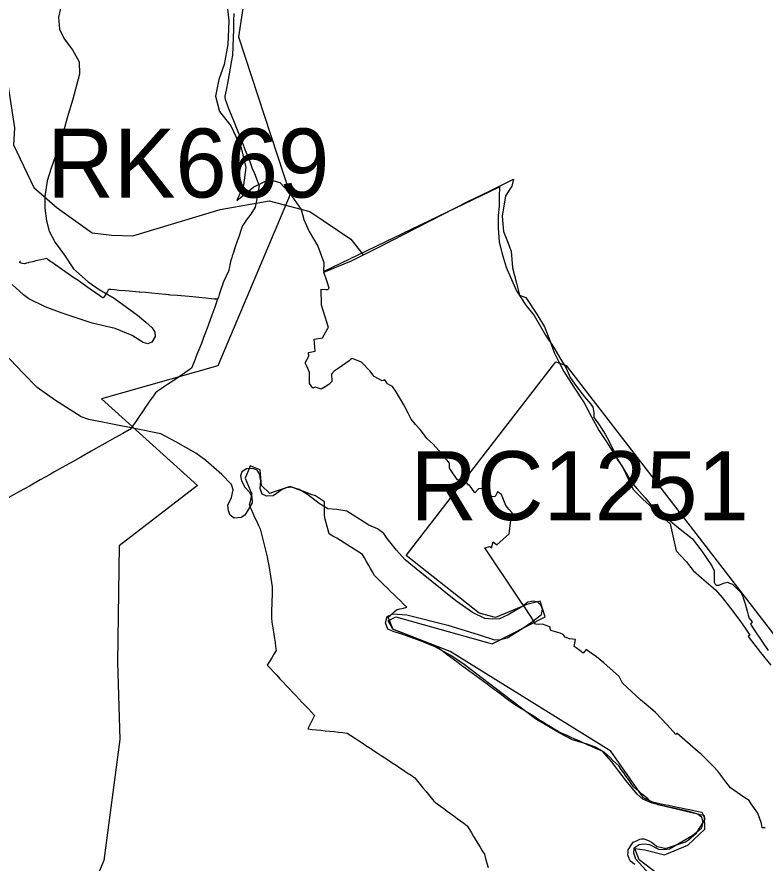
# Model space of a CAD drawing. Extents: x -789162 to -606354, y -1062736 to -945481.
# Drawn here: x -682484 to -680858, y -988999 to -987160 of the extents above; entities that cross this region are included whole.
import ezdxf

# ---------------------------------------------------------------- set-up
doc = ezdxf.new("R2010")
doc.units = 0
for name, color, linetype in [('_SIRSI VZTAHY_CYKLOTRASY MISTNI S', 7, 'Continuous'), ('_SIRSI VZTAHY_NATURA_EVL', 7, 'Continuous'), ('_SIRSI VZTAHY_OP vodnich zdroju II stupne', 7, 'Continuous'), ('_SIRSI VZTAHY_PRIRODNIHO PARKU', 7, 'Continuous'), ('_SIRSI VZTAHY_SILNICE III TRIDY_STAV', 7, 'Continuous'), ('_SIRSI VZTAHY_USES_popis S', 7, 'Continuous'), ('_SIRSI VZTAHY_USES_RBC_S', 7, 'Continuous'), ('_SIRSI VZTAHY_USES_RBK_S', 7, 'Continuous'), ('_SIRSI VZTAHY_VTL PLYNOVOD', 7, 'Continuous')]:
    doc.layers.add(name, color=color, linetype=linetype)

msp = doc.modelspace()

# ---------------------------------------------------------------- linework, layer by layer
at = {"layer": '_SIRSI VZTAHY_CYKLOTRASY MISTNI S'}
msp.add_lwpolyline([(-681958.5, -986912.3), (-682002.9, -987203.1), (-681890.1, -987545.3), (-682047.4, -987918.3), (-682300.4, -987990.2), (-682091.8, -988178.4), (-682261.9, -988309.2), (-682265.4, -988562.4), (-682260.7, -988730.8), (-682295.3, -988993.7), (-682321.8, -989054.9)], dxfattribs=at)
at = {"layer": '_SIRSI VZTAHY_NATURA_EVL'}
msp.add_lwpolyline([(-681141.3, -989002.4), (-681146.2, -988998.5), (-681151.2, -988994.6), (-681154.6, -988986), (-681156.1, -988981.6), (-681155.6, -988976.6), (-681155.6, -988970.2), (-681152.9, -988966.3), (-681148.7, -988960.1), (-681144.5, -988954), (-681142.6, -988952.8), (-681139.1, -988951.8), (-681137.1, -988951), (-681130.1, -988947.3), (-681127.2, -988946.8), (-681121, -988946.3), (-681115.7, -988948.7), (-681110.1, -988951.1), (-681104.5, -988953.6), (-681098.9, -988958.3), (-681093.2, -988963.1), (-681085, -988964.9), (-681076.8, -988966.7), (-681076.1, -988966.6), (-681075.4, -988967), (-681074.3, -988967.2), (-681065.6, -988964.5), (-681056.8, -988961.7), (-681048.1, -988958.9), (-681039.3, -988956.1), (-681030.6, -988953.4), (-681024.7, -988948.6), (-681018.8, -988943.8), (-681012.9, -988938.9), (-681007.1, -988934.1), (-681002.3, -988926.4), (-680997.5, -988918.7), (-680992.7, -988910.9), (-680987.9, -988903.2), (-680991.1, -988896.3), (-680994.3, -988889.3), (-681003.4, -988887.5), (-681012.6, -988885.7), (-681021.7, -988883.8), (-681030.9, -988882), (-681040, -988880.2), (-681049.2, -988878.3), (-681058.3, -988876.5), (-681067.7, -988874.4), (-681077.1, -988872.3), (-681086.5, -988870.1), (-681095.9, -988868), (-681105.3, -988865.8), (-681111.7, -988860.5), (-681118.1, -988855.2), (-681124.5, -988849.8), (-681130.9, -988844.5), (-681137.3, -988839.2), (-681143.7, -988833.8), (-681149, -988826.2), (-681154.3, -988818.5), (-681159.7, -988810.9), (-681165, -988803.2), (-681170.4, -988795.6), (-681175.7, -988787.9), (-681182.1, -988782), (-681188.5, -988776), (-681194.9, -988770), (-681201.3, -988764), (-681207.7, -988758.1), (-681216.8, -988754), (-681225.9, -988749.9), (-681235.1, -988745.8), (-681244.2, -988741.8), (-681253.3, -988737.7), (-681262.4, -988733.6), (-681271.5, -988729.5), (-681280.7, -988725.5), (-681289.8, -988721.4), (-681298.9, -988717.3), (-681308, -988713.2), (-681316.3, -988708.1), (-681324.6, -988702.9), (-681332.8, -988697.8), (-681341.1, -988692.6), (-681349.4, -988687.5), (-681357.6, -988682.3), (-681365.9, -988677.1), (-681374.2, -988672), (-681382.5, -988666.8), (-681390.7, -988661.7), (-681399, -988656.5), (-681407.3, -988651.3), (-681415.1, -988645.5), (-681423, -988639.7), (-681430.9, -988633.8), (-681438.8, -988628), (-681446.7, -988622.1), (-681454.5, -988616.3), (-681462.4, -988610.4), (-681470.3, -988604.6), (-681478.2, -988598.7), (-681486, -988592.9), (-681493.9, -988587.1), (-681501.8, -988581.2), (-681509.7, -988575.4), (-681517.5, -988569.5), (-681525.4, -988563.7), (-681533.3, -988557.8), (-681541.2, -988552), (-681549, -988546.2), (-681556.9, -988540.3), (-681564.8, -988534.5), (-681572.7, -988528.6), (-681581.2, -988525.1), (-681589.8, -988521.5), (-681598.3, -988517.9), (-681606.8, -988514.4), (-681615.4, -988510.8), (-681623.9, -988507.3), (-681632.4, -988504.1), (-681641, -988500.9), (-681649.5, -988497.7), (-681658.1, -988494.5), (-681666.6, -988491.3), (-681670.1, -988482.4), (-681673.7, -988473.5), (-681677.3, -988464.6), (-681671.2, -988459.3), (-681665.2, -988453.9), (-681659.1, -988448.6), (-681651.6, -988446.8), (-681644.2, -988445), (-681636.7, -988443.2), (-681643.8, -988436.3), (-681650.8, -988429.4), (-681657.8, -988422.4), (-681664.9, -988415.5), (-681671.9, -988408.6), (-681679, -988401.6), (-681686, -988394.7), (-681693.1, -988387.8), (-681700.1, -988380.8), (-681707.1, -988373.9), (-681711.4, -988366.2), (-681715.7, -988358.6), (-681719.9, -988350.9), (-681724.2, -988343.3), (-681728.5, -988335.6), (-681732.8, -988328), (-681740.8, -988323), (-681748.9, -988318), (-681756.9, -988313.1), (-681765, -988308.1), (-681773.1, -988303.1), (-681781.1, -988298.1), (-681789.2, -988293.1), (-681797.3, -988288.2), (-681805.3, -988283.2), (-681807.5, -988275.3), (-681809.6, -988267.4), (-681811.7, -988259.5), (-681813.9, -988251.6), (-681816, -988243.7), (-681816, -988233.7), (-681816, -988223.8), (-681816, -988213.8), (-681822.4, -988209.5), (-681828.8, -988205.3), (-681835.2, -988201), (-681844.3, -988197.6), (-681853.5, -988194.2), (-681862.6, -988190.8), (-681871.8, -988187.4), (-681880.9, -988184), (-681890.1, -988180.6), (-681898.9, -988183.6), (-681907.7, -988186.5), (-681916.6, -988189.5), (-681925.4, -988192.4), (-681934.2, -988195.4), (-681940.3, -988189.8), (-681946.5, -988184.2), (-681952.6, -988178.6), (-681953.4, -988170.1), (-681954.2, -988161.5), (-681955, -988153), (-681955.8, -988144.4), (-681962.9, -988141.6), (-681970, -988138.7), (-681977.1, -988135.9), (-681980.7, -988144.8), (-681984.3, -988153.7), (-681987.8, -988162.6), (-681984.3, -988171.1), (-681980.9, -988179.7), (-681977.4, -988188.2), (-681973.9, -988196.7), (-681975.7, -988204.9), (-681977.5, -988213.1), (-681979.3, -988221.3), (-681975.4, -988229.8), (-681971.4, -988238.4), (-681967.5, -988246.9), (-681963.6, -988255.4), (-681959.7, -988264), (-681955.8, -988272.5), (-681953.6, -988281.2), (-681951.3, -988290), (-681949.1, -988298.7), (-681946.8, -988307.5), (-681944.6, -988316.2), (-681942.4, -988325), (-681940.1, -988333.7), (-681938.5, -988343), (-681937, -988352.2), (-681935.4, -988361.5), (-681933.8, -988370.7), (-681932.3, -988379.9), (-681930.7, -988389.2), (-681929.1, -988398.4), (-681929.4, -988408.2), (-681929.7, -988417.9), (-681930, -988427.7), (-681930.3, -988437.5), (-681930.6, -988447.2), (-681930.9, -988457), (-681931.2, -988466.7), (-681929.9, -988475.5), (-681928.6, -988484.3), (-681927.2, -988493.1), (-681925.9, -988501.9), (-681924.6, -988510.7), (-681923.2, -988519.6), (-681921.9, -988528.4), (-681920.6, -988537.2), (-681925.5, -988545.2), (-681930.3, -988553.2), (-681935.2, -988561.2), (-681940.1, -988569.2), (-681933.2, -988576.5), (-681926.4, -988583.8), (-681919.5, -988591), (-681912.6, -988598.3), (-681905.8, -988605.6), (-681898.9, -988612.8), (-681892, -988620.1), (-681885.2, -988627.3), (-681878.3, -988634.6), (-681871.4, -988641.9), (-681864.6, -988649.1), (-681857.7, -988656.4), (-681850.8, -988663.7), (-681843.9, -988670.9), (-681837.1, -988678.2), (-681840.8, -988685.5), (-681844.4, -988692.9), (-681848.1, -988700.3), (-681851.8, -988707.6), (-681842.3, -988708.6), (-681832.8, -988709.6), (-681823.3, -988710.6), (-681813.9, -988711.5), (-681804.4, -988712.5), (-681794.9, -988713.5), (-681785.4, -988714.5), (-681775.9, -988715.5), (-681766.4, -988716.5), (-681758.2, -988721.8), (-681750.1, -988727.2), (-681741.9, -988732.6), (-681733.7, -988738), (-681725.5, -988743.4), (-681717.4, -988748.8), (-681709.2, -988754.2), (-681701, -988759.6), (-681692.8, -988765), (-681684.6, -988770.4), (-681676.5, -988775.8), (-681668.3, -988781.2), (-681660.1, -988786.6), (-681651.9, -988792), (-681643.8, -988797.4), (-681635.6, -988802.8), (-681627.4, -988808.2), (-681619.2, -988813.6), (-681613.3, -988820.9), (-681607.4, -988828.2), (-681601.6, -988835.5), (-681595.7, -988842.8), (-681589.8, -988850.2), (-681583.9, -988857.5), (-681578, -988864.8), (-681570.8, -988870.1), (-681563.5, -988875.5), (-681556.2, -988880.8), (-681549, -988886.1), (-681541.7, -988891.5), (-681534.5, -988896.8), (-681527.2, -988902.1), (-681520, -988907.5), (-681512.7, -988912.8), (-681505.4, -988918.1), (-681500.8, -988925.9), (-681496.1, -988933.6), (-681491.4, -988941.3), (-681486.8, -988949.1), (-681482.1, -988956.8), (-681477.4, -988964.6), (-681472.8, -988972.3), (-681468.1, -988980), (-681465.4, -988989.6), (-681462.8, -988999.2), (-681460.1, -989008.8)], dxfattribs=at)
at = {"layer": '_SIRSI VZTAHY_OP vodnich zdroju II stupne'}
msp.add_lwpolyline([(-680666.4, -989347.1), (-681131.4, -988992.2), (-681140.7, -988967.6), (-681119.3, -988970.2), (-681076.6, -988981.2), (-681025.7, -988960.4), (-680989, -988925.6), (-680989.5, -988896.8), (-681090.2, -988872.9), (-681121.9, -988857.5), (-681193.5, -988755.8), (-681542.5, -988539.2), (-681667.4, -988490.8), (-681676.9, -988472.2), (-681660.4, -988464.2), (-681451, -988522.3), (-681336.1, -988464), (-681347, -988429.5), (-681376.1, -988437.1), (-681443.6, -988465.3), (-681479.5, -988456.2), (-681638.4, -988330.2), (-681313.1, -987909.4), (-681290.2, -987917.1), (-680724.2, -988650.9)], dxfattribs=at)
at = {"layer": '_SIRSI VZTAHY_PRIRODNIHO PARKU'}
msp.add_lwpolyline([(-682029.7, -987115.8), (-682023.6, -987168.2), (-682025.6, -987219.6), (-682033.9, -987262.7), (-682045.2, -987295.6), (-682052.3, -987331.5), (-682044.1, -987365.4), (-682019.5, -987396.2), (-681996.9, -987444.5), (-681986.6, -987486.6), (-681991.7, -987525.6), (-682006.1, -987558.5), (-681969.1, -987528.7), (-681936.3, -987513.3), (-681912.7, -987519.5), (-681892.1, -987542.1), (-681866.4, -987578), (-681860.3, -987599.6), (-681849, -987626.3), (-681830.5, -987658.1), (-681817.1, -987693.1), (-681818.1, -987713.2), (-681435.1, -987529.2), (-681436.1, -987551), (-681436.1, -987571.2), (-681438.4, -987591.3), (-681438.4, -987618.2), (-681436.1, -987649.6), (-681429.4, -987674.3), (-681420.4, -987703.4), (-681409.2, -987730.3), (-681398, -987754.9), (-681377.8, -987786.3), (-681359.9, -987808.7), (-681335.3, -987851.3), (-681317.3, -987878.2), (-681303.9, -987900.6), (-681290.4, -987923), (-681281.5, -987943.2), (-681268, -987963.4), (-681250.1, -987985.8), (-681236.7, -988001.5), (-681232.2, -988008.2), (-681229.9, -988019.4), (-681229.9, -988030.6), (-681223.2, -988039.6), (-681214.2, -988053), (-681205.3, -988066.5), (-681198.6, -988079.9), (-681187.4, -988102.3), (-681178.4, -988122.5), (-681169.4, -988135.9), (-681159.3, -988153.2), (-681148.1, -988171.2), (-681136.9, -988184.6), (-681118.9, -988204.8), (-681107.7, -988218.2), (-681094.3, -988229.4), (-681080.8, -988240.6), (-681065.1, -988254.1), (-681049.4, -988267.5), (-681029.3, -988283.2), (-681015.8, -988294.4), (-681006.9, -988305.6), (-680995.7, -988321.3), (-680984.5, -988337), (-680973.3, -988352.7), (-680968.8, -988363.9), (-680968.8, -988379.6), (-680968.8, -988388.5), (-680966.5, -988393), (-680964.3, -988395.3), (-680957.6, -988395.3), (-680948.6, -988390.8), (-680939.6, -988388.5), (-680935.2, -988390.8), (-680928.4, -988393), (-680921.7, -988399.8), (-680915, -988406.5), (-680910.5, -988411), (-680906, -988419.9), (-680905.3, -988422.6), (-680901.5, -988435.6), (-680897.1, -988451.3), (-680894.8, -988460.3), (-680892.6, -988467), (-680886.3, -988474.9), (-680889.3, -988479.6), (-680877.4, -988498.7), (-680851.1, -988536.9)], dxfattribs=at)
at = {"layer": '_SIRSI VZTAHY_SILNICE III TRIDY_STAV'}
for points in [[(-682388.3, -987134.8), (-682393.9, -987159.7), (-682391.5, -987185.9), (-682381.6, -987207), (-682363.7, -987231.4), (-682348.8, -987256.8), (-682348.1, -987284.2), (-682362.9, -987338.2), (-682374.9, -987378.7), (-682387.6, -987424.7), (-682409.6, -987488), (-682418.3, -987515.6), (-682423.4, -987550), (-682423.8, -987575.3), (-682420.2, -987602.5), (-682413.9, -987625.4), (-682401.4, -987650.2), (-682381.1, -987677.3), (-682361.4, -987707.2), (-682329.3, -987735.2), (-682305.7, -987752.3), (-682272.9, -987771), (-682222.5, -987807.8), (-682204.2, -987823.5), (-682190.1, -987835.8), (-682184.6, -987844.7), (-682184.1, -987854.6), (-682190.9, -987866.5), (-682199.5, -987870), (-682210.2, -987867.4), (-682234.1, -987851.9), (-682270.7, -987836.6), (-682320.6, -987825.2), (-682385.8, -987803.4), (-682423.1, -987789.8), (-682458.4, -987772.8), (-682469.9, -987763.5), (-682494.9, -987741.1)], [(-681095.8, -989037.8), (-681138.7, -988990.5), (-681143, -988977.4), (-681142.4, -988966.3), (-681131.7, -988958.8), (-681120.4, -988957.3), (-681108.8, -988959), (-681089.8, -988969.2), (-681075.7, -988969.7), (-681065.7, -988968.2), (-681014.7, -988938.7), (-680995.6, -988922.5), (-680992.7, -988910.7), (-680995.5, -988900.3), (-681004.2, -988893), (-681022.8, -988887.3), (-681079.3, -988874.6), (-681103.7, -988869.2), (-681123.4, -988860), (-681135.7, -988849.1), (-681160.2, -988820.6), (-681191.7, -988778.1), (-681211, -988755.8), (-681226.2, -988747.1), (-681244.6, -988741), (-681276.5, -988731.4), (-681305.7, -988715.8), (-681357.1, -988685.4), (-681444.3, -988618.9), (-681512, -988567.8), (-681540.9, -988547.9), (-681576.6, -988528.1), (-681611.1, -988514.5), (-681645.5, -988502.2), (-681663.9, -988496.4), (-681678.1, -988490.4), (-681682.8, -988476.9), (-681679.7, -988463.4), (-681667, -988457.1), (-681636.5, -988459.8), (-681547.2, -988481.8), (-681479.3, -988503.1), (-681446.3, -988513.9), (-681433.3, -988513), (-681418.4, -988509.5), (-681386.9, -988490.1), (-681365.6, -988475.6), (-681344.1, -988459.1), (-681341.5, -988447.2), (-681345.3, -988438.6), (-681352.2, -988431.7), (-681361.1, -988429.8), (-681373.8, -988432), (-681384.6, -988440.7), (-681416.6, -988459.8), (-681435.2, -988468.1), (-681451.4, -988469.1), (-681467, -988467.2), (-681493.9, -988454.5), (-681529.8, -988428.8), (-681608.6, -988365.9), (-681640.6, -988340.2), (-681659, -988318.7), (-681679.3, -988293.8), (-681686.7, -988282.9), (-681700.1, -988272.2), (-681719.6, -988264.7), (-681739.8, -988251.2), (-681767.2, -988233.8), (-681788.9, -988230.3), (-681808.1, -988229.4), (-681827.2, -988217.1), (-681852.3, -988197.9), (-681870.4, -988187.1), (-681887.1, -988182.2), (-681899.2, -988183.2), (-681907.8, -988187.1), (-681927.4, -988201.1), (-681941.7, -988201.4), (-681951, -988197.4), (-681955.4, -988185.1), (-681954.4, -988168), (-681956.9, -988152.6), (-681962.3, -988145.3), (-681971.5, -988141.5), (-681985.3, -988141.9), (-681995.6, -988148.7), (-681998.5, -988157.6), (-681996.2, -988168), (-681988.6, -988182.2), (-681979.4, -988191.8), (-681973.7, -988201.9), (-681972.9, -988216.1), (-681980.7, -988229.7), (-681988.9, -988242.8), (-681996.7, -988248), (-682011.8, -988249.1), (-682020.8, -988243.1), (-682024.7, -988233.3), (-682025.8, -988221.2), (-682017.8, -988204.7), (-682014.3, -988187.5), (-682017.8, -988176.4), (-682038.9, -988154.7), (-682073.7, -988124), (-682095.4, -988107.7), (-682139, -988083.4), (-682171.5, -988066.2), (-682229, -988054.2), (-682328.3, -988034.8), (-682344.5, -988028.8), (-682400.1, -987993.7), (-682440.3, -987965.1), (-682471.1, -987933.6), (-682511.9, -987890.5)]]:
    msp.add_lwpolyline(points, dxfattribs=at)
at = {"layer": '_SIRSI VZTAHY_USES_RBC_S'}
msp.add_lwpolyline([(-680857.4, -988922.3), (-680864.1, -988922.9), (-680865.8, -988913.4), (-680873.6, -988891), (-680888.4, -988870.1), (-680892.7, -988863.3), (-680904.3, -988856.1), (-680933.4, -988835.7), (-680943.5, -988822.8), (-680951.9, -988811.2), (-680960.3, -988799.6), (-680969.5, -988790), (-680978.6, -988780.5), (-680988.2, -988771.1), (-680997.8, -988761.8), (-681003.3, -988757.1), (-681026.6, -988737.1), (-681049.8, -988717.1), (-681051.9, -988720), (-681070.6, -988698.8), (-681096, -988671.5), (-681112.4, -988657.9), (-681128.9, -988644.4), (-681148.6, -988625.9), (-681168, -988608.3), (-681175, -988593.6), (-681208.4, -988563.9), (-681216.2, -988557.5), (-681224.1, -988551), (-681235.6, -988543.1), (-681247.1, -988535.1), (-681253, -988542.6), (-681260.8, -988536.7), (-681268.6, -988530.9), (-681272.6, -988528.3), (-681271.3, -988520.8), (-681270, -988513.4), (-681283.4, -988511.4), (-681292.7, -988508.2), (-681296.8, -988502.5), (-681303.3, -988499.4), (-681313.3, -988496.6), (-681323.4, -988493.9), (-681325.6, -988485.9), (-681341.7, -988480), (-681351.4, -988480.5), (-681356.9, -988479.8), (-681365.6, -988465.2), (-681382.2, -988440), (-681387.8, -988432.1), (-681397, -988418.6), (-681467.1, -988313.9), (-681456.1, -988310.9), (-681452.8, -988313.6), (-681448.8, -988300.8), (-681440.7, -988307.1), (-681414.3, -988283.6), (-681411.8, -988265.3), (-681409, -988245.4), (-681407.9, -988237.4), (-681414.9, -988229.5), (-681421.8, -988221.6), (-681431.1, -988198), (-681439.9, -988191.9), (-681444.9, -988202), (-681467.4, -988204.2), (-681462.3, -988184.3), (-681480.6, -988185.3), (-681489.2, -988194.2), (-681500.1, -988177.8), (-681502.6, -988177.6), (-681505.7, -988173), (-681515.4, -988167.5), (-681518.1, -988170.7), (-681526.2, -988166.3), (-681535, -988153.4), (-681543.8, -988140.5), (-681543.7, -988136.8), (-681544.2, -988136.2), (-681543.7, -988129.8), (-681556.5, -988114.6), (-681568.1, -988101.7), (-681579.6, -988088.8), (-681586.3, -988082.5), (-681593.1, -988076.1), (-681600.5, -988066.2), (-681608, -988056.4), (-681617.8, -988045.4), (-681627.6, -988034.4), (-681633.9, -988020.9), (-681643.5, -988002.6), (-681652.6, -987986.8), (-681660.2, -987975), (-681667.9, -987963.2), (-681673.4, -987960.1), (-681678.9, -987957), (-681684.5, -987948.4), (-681690, -987950.5), (-681707.5, -987941.1), (-681717.3, -987929.3), (-681735.3, -987910), (-681755.8, -987902.3), (-681759.1, -987904.2), (-681762.2, -987906.9), (-681784.1, -987922.2), (-681795, -987930), (-681800.4, -987936.5), (-681799.8, -987952.5), (-681806.2, -987958.6), (-681814.5, -987964), (-681822.7, -987969.2), (-681835.8, -987964.2), (-681840.8, -987967), (-681848.4, -987956.2), (-681848.3, -987944.3), (-681848.2, -987932.3), (-681853.7, -987920), (-681857.4, -987911.3), (-681849.8, -987897.1), (-681850.4, -987888.9), (-681835.6, -987886.1), (-681837.8, -987859.8), (-681820, -987857.2), (-681808.8, -987838), (-681807.1, -987834.8), (-681814.3, -987811.4), (-681822, -987785.9), (-681822.5, -987783.8), (-681822.6, -987751.7), (-681812.5, -987751.8), (-681810.1, -987751.8), (-681808.5, -987751.8), (-681805.4, -987749.5), (-681810.5, -987733.5), (-681817.4, -987714.4), (-681757.1, -987689.6), (-681697.3, -987660.3), (-681504, -987560.8), (-681454.4, -987536.7), (-681404.9, -987512.6), (-681408.1, -987527.6), (-681422.4, -987548.7), (-681429.3, -987592.8), (-681426.2, -987626.1), (-681418.1, -987647.5), (-681410, -987669), (-681407, -987705.3), (-681398.5, -987738.4), (-681391.9, -987764.3), (-681377.9, -987769.8), (-681354.4, -987805.9), (-681337.1, -987833.2), (-681326.6, -987861), (-681316.1, -987888.8), (-681305.9, -987909.5), (-681295.7, -987930.3), (-681273.5, -987964.6), (-681251.3, -987998.9), (-681234.9, -988029), (-681218.5, -988059.2), (-681202.9, -988083.7), (-681166.5, -988140.6), (-681144.8, -988187), (-681134.4, -988197.3), (-681124, -988207.7), (-681094.1, -988234.6), (-681064.2, -988261.5), (-681051.2, -988320.7), (-681029.8, -988343.5), (-681014.5, -988363.3), (-680996.1, -988379.1), (-680965.9, -988405.5), (-680951.1, -988421.6), (-680932.8, -988445.3), (-680914.6, -988468.9), (-680902.9, -988486.5), (-680891.2, -988503.9), (-680894.4, -988506.4), (-680867.7, -988541.6), (-680845.7, -988568.8)], dxfattribs=at)
at = {"layer": '_SIRSI VZTAHY_USES_RBK_S'}
msp.add_lwpolyline([(-682748.5, -987131.5), (-682630.5, -987190.4), (-682551.6, -987223.4), (-682520.4, -987246.8), (-682503.1, -987311), (-682489.2, -987400.4), (-682491.8, -987437.7), (-682447.6, -987530.6), (-682396.5, -987574.8), (-682321, -987628.6), (-682277.7, -987633.8), (-682232.6, -987635.5), (-682042.7, -987578.3), (-681936.1, -987559.2), (-681847.6, -987582.6), (-681758.3, -987642.5), (-681731.7, -987677.1)], dxfattribs=at)
at = {"layer": '_SIRSI VZTAHY_VTL PLYNOVOD'}
for points in [[(-682012.9, -987152.3), (-682013.3, -987167.4), (-682013.7, -987174.4), (-682013.6, -987177.5), (-682013.4, -987187.2), (-682015.8, -987242.7), (-682017.7, -987253.9), (-682020.7, -987271), (-682023, -987283.3), (-682026, -987300.1), (-682029.7, -987319), (-682032.1, -987331.8), (-682032.6, -987334.8), (-682031.7, -987338.6), (-682024, -987358.6), (-682018.4, -987372.2), (-682011.9, -987388.4), (-682005.5, -987404.8), (-681999.1, -987421.2), (-681992.5, -987437.9), (-681988.1, -987449.2), (-681982.9, -987461.8), (-681978.3, -987473.9), (-681972.6, -987488.8), (-681968, -987499.9), (-681964.3, -987509.4), (-681959.6, -987521.3), (-681958, -987526.5), (-681960.8, -987541.4), (-681963.8, -987558.5), (-681966.1, -987573), (-681975.9, -987588.2), (-681985.8, -987601.7), (-681990.4, -987608.4), (-681993.6, -987612.9), (-681997.4, -987623.9), (-682001.5, -987635.8), (-682006.2, -987649.3), (-682009.5, -987659.4), (-682013.7, -987671.8), (-682015.6, -987677.6), (-682016.2, -987679.2), (-682016.5, -987680), (-682017.2, -987682.5), (-682020.1, -987691.3), (-682023.3, -987710.1), (-682024, -987712.2), (-682034.6, -987733.9), (-682035.2, -987735.8), (-682041.6, -987754.2), (-682044.6, -987763.3), (-682046.2, -987768.5), (-682047.5, -987772.2), (-682048.2, -987773.5)], [(-682478.3, -987692.4), (-682478.9, -987692.7), (-682478.8, -987692.9), (-682478.7, -987693.2), (-682478.6, -987693.3), (-682478, -987693)], [(-682476.8, -987691), (-682477, -987691.1), (-682477.6, -987691.5), (-682477.6, -987691.5), (-682478.4, -987692), (-682478.3, -987692.2), (-682478.3, -987692.4)], [(-682478.3, -987692.4), (-682478.1, -987692.7), (-682478, -987693)], [(-682053.7, -987773), (-682053.9, -987773), (-682053.9, -987773), (-682054.8, -987772.9), (-682061.6, -987772.4), (-682073.5, -987771), (-682088.5, -987769.6), (-682102, -987768), (-682118.3, -987766.8), (-682135.9, -987765.3), (-682150.5, -987764.2), (-682153.5, -987763.8), (-682154.7, -987763.7), (-682155.8, -987763.6), (-682159.5, -987763.3), (-682161.3, -987763.1), (-682176.8, -987761.7), (-682191.7, -987760.4), (-682205.1, -987759), (-682217.4, -987758.2), (-682218.2, -987758.1), (-682240.3, -987756.1), (-682248.8, -987755.2), (-682261.9, -987754.2), (-682272, -987753.2), (-682280.5, -987752.3), (-682284.1, -987752.1), (-682285.6, -987753.3), (-682288.2, -987757.6), (-682292.8, -987764.7), (-682294, -987766.6), (-682295.8, -987769.6), (-682296.6, -987770.2), (-682297.4, -987770.4), (-682299, -987769.3), (-682303.9, -987766.1), (-682313.6, -987759.2), (-682325, -987751.2), (-682335.4, -987744.4), (-682340.4, -987740.6), (-682351.4, -987732.8), (-682360.5, -987726.6), (-682380.2, -987712.8), (-682392.4, -987704.5), (-682399.5, -987699.4), (-682407.5, -987693.7), (-682410.4, -987691.8), (-682416.6, -987687.6), (-682419.6, -987685.1), (-682432.2, -987687.6), (-682443.2, -987690.1), (-682449.7, -987691.7), (-682458.2, -987693.8), (-682459.4, -987693.9), (-682463.2, -987695), (-682468, -987696), (-682472, -987695.8), (-682475.1, -987695), (-682477.2, -987694), (-682477.9, -987693.3), (-682478, -987693)], [(-682048.2, -987773.5), (-682054.1, -987790.9), (-682058.1, -987802.5), (-682070.4, -987836.2), (-682074, -987845.5), (-682078.5, -987856.8), (-682083.1, -987869.5), (-682088.7, -987883.3), (-682092.9, -987893.2), (-682099.3, -987909.6), (-682104.5, -987923.1), (-682104.6, -987923.4), (-682109.5, -987926.5), (-682139, -987946.8), (-682144.7, -987950.9), (-682148.3, -987952.9), (-682149.3, -987953.6), (-682151.1, -987954.9), (-682157.1, -987958.4), (-682163.4, -987962.7), (-682170.4, -987968.2), (-682179.1, -987974), (-682183.3, -987977), (-682187.4, -987983.1), (-682195.8, -987995), (-682203.1, -988005.7), (-682205.5, -988008.8), (-682210.9, -988016.9), (-682218.7, -988028.3), (-682227.3, -988041.2), (-682233.1, -988049.3), (-682234.1, -988050.6), (-682238.2, -988056.3), (-682238.7, -988056.8), (-682238.7, -988056.9), (-682240.4, -988057.6), (-682253.8, -988065.1), (-682271.4, -988074.8), (-682299.8, -988090.9), (-682304.9, -988093.7), (-682305, -988093.7), (-682305.7, -988094.1), (-682306, -988094.3), (-682322.8, -988104), (-682345.3, -988116.6), (-682370.1, -988130.5), (-682386.1, -988139.5), (-682404, -988149.4), (-682412.1, -988154.1), (-682433.8, -988166.3), (-682457.3, -988179.5), (-682478.9, -988191.5), (-682503.4, -988205.4)], [(-682052.7, -987773.1), (-682052.6, -987772.7), (-682052.8, -987772.6), (-682053.3, -987772.6), (-682053.6, -987772.6), (-682053.7, -987773)], [(-682052.7, -987773.1), (-682052.9, -987773.1), (-682053.2, -987773), (-682053.5, -987773), (-682053.7, -987773)], [(-682048.2, -987773.5), (-682051.9, -987773.1), (-682052.2, -987773.1), (-682052.7, -987773.1)]]:
    msp.add_lwpolyline(points, dxfattribs=at)

# ---------------------------------------------------------------- texts
at = {"layer": '_SIRSI VZTAHY_USES_popis S'}
for s, p in [('RK669', (-682418.4, -987552.2)), ('RC1251', (-681629.2, -988253.7))]:
    msp.add_text(s, height=150, dxfattribs=at).set_placement(p)

doc.saveas('drawing.dxf')
